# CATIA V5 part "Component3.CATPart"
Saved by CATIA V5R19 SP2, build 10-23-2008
Part number: Component3
Definition: Component3
Nomenclature: Component3
Source: Unknown
Bounding box of the stored display mesh (mm): x -4.283 to 0.4, y 0 to 2.367, z 0 to 3.3
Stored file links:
  Z:\fausse table rondelle-20220905T211342Z-001\fausse table rondelle\Component3.CATPart
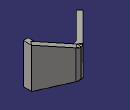
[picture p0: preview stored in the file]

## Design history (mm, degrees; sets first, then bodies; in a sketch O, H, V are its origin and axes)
AxisSystem1: origin (0, 0, 0), X (1, 0, 0), Y (0, 1, 0), Z (0, 0, 1)
Body1 "Body1" (main body)
  Solid1: solid without history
